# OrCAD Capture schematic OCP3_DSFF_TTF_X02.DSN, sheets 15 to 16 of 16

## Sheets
15 PAGE16 - 3V3 REGULATOR: size Custom
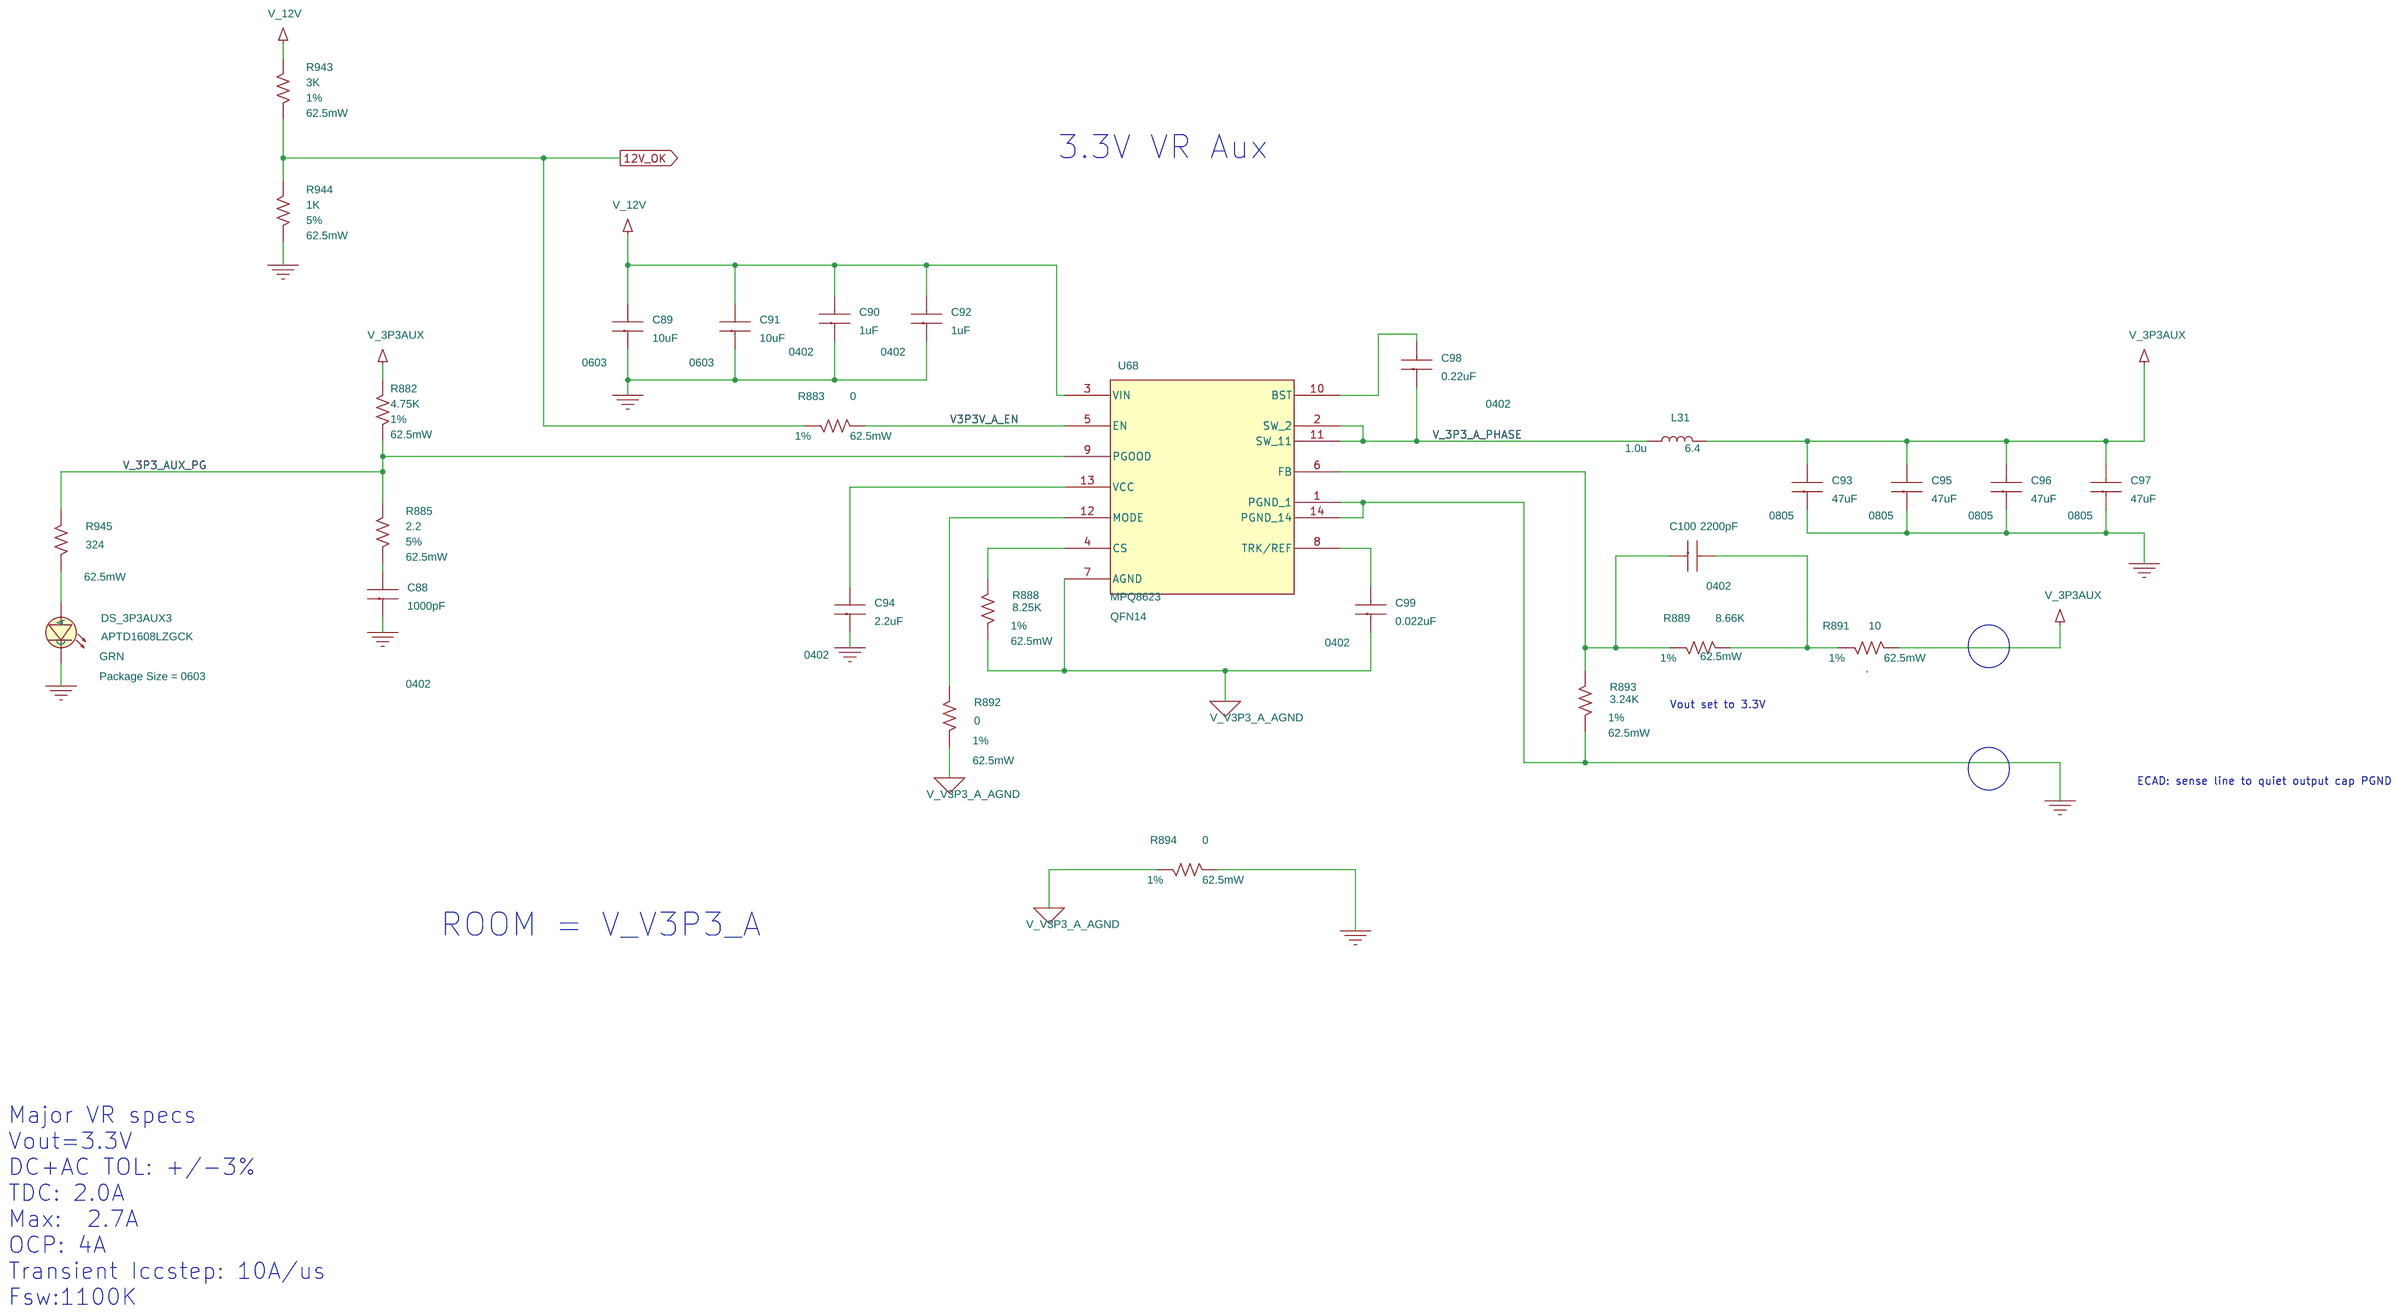
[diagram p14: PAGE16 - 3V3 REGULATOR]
16 PAGE09 - Secondary M-XIO/PICPWR: size Custom
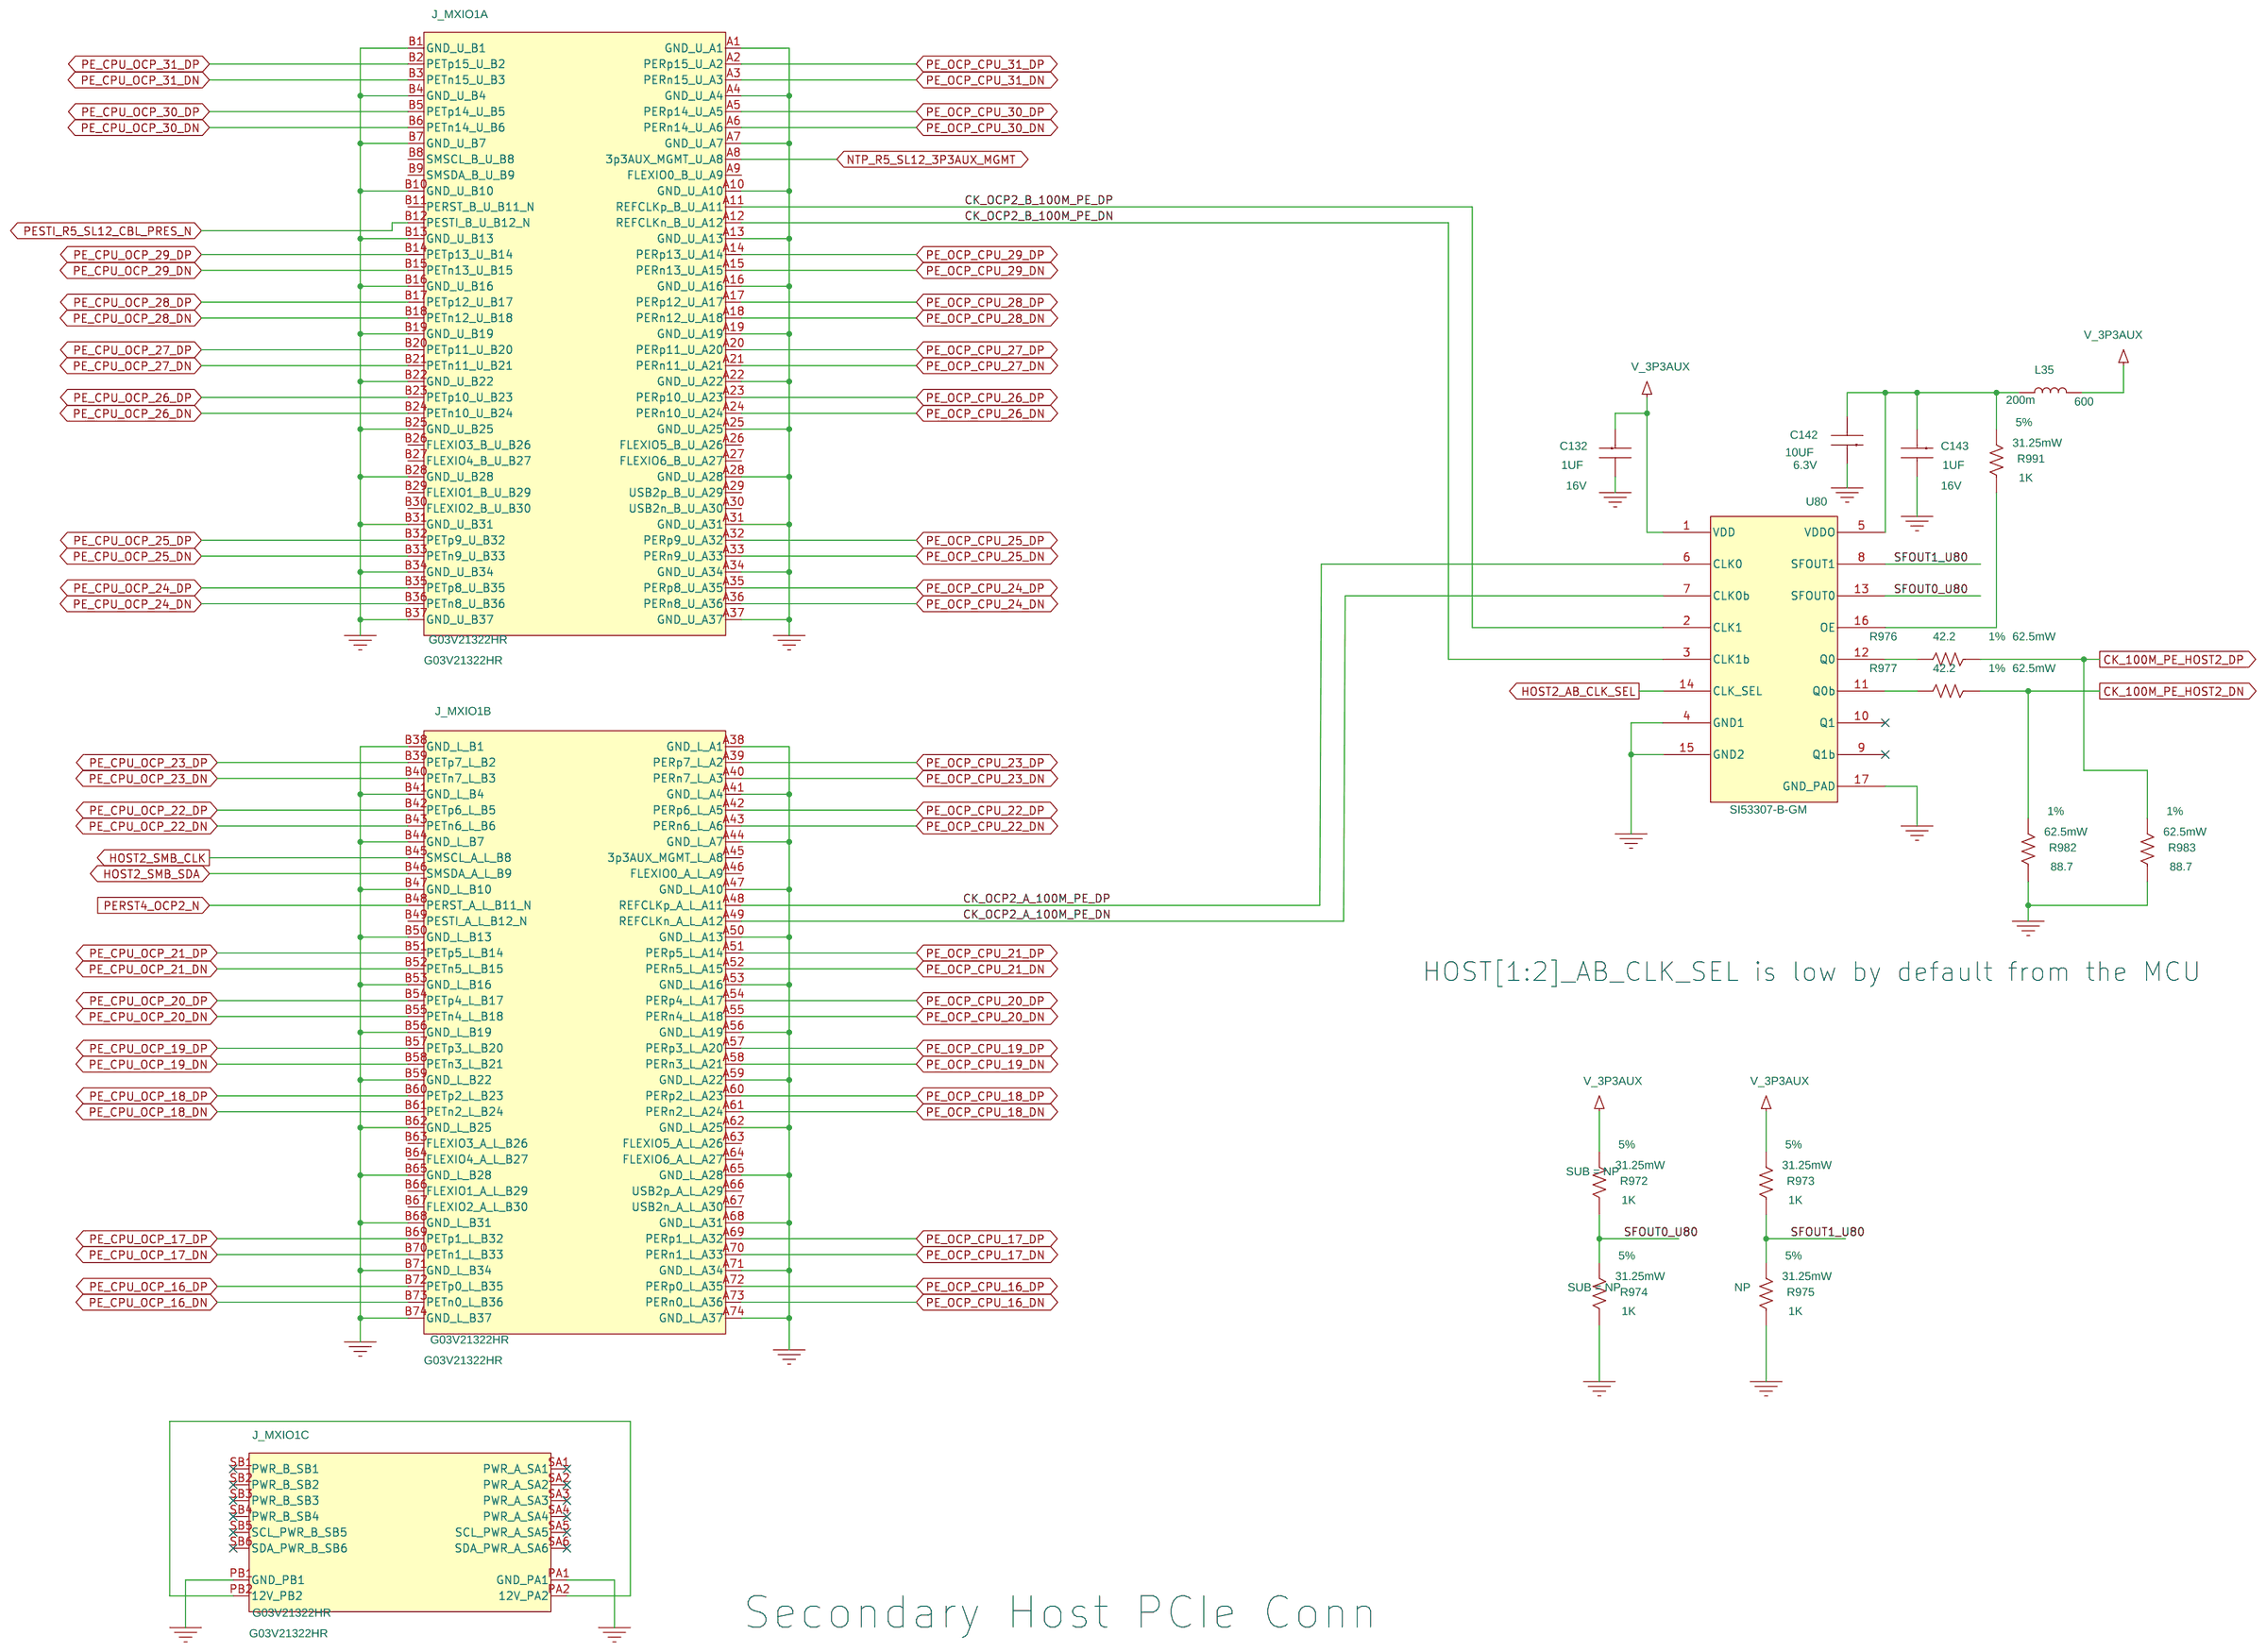
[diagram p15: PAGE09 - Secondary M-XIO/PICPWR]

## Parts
sheet PAGE09 - Secondary M-XIO/PICPWR
C132  1UF  [C0603]
C142  10UF  [C0603]
C143  1UF  [C0603]
J_MXIO1  G03V21322HR  [AMPHENOL_G03V21322HR]  (sections A,B,C)
L35  600  [FR0603]
R972  1K  [R0402]
R973  1K  [R0402]
R974  1K  [R0402]
R975  1K  [R0402]
R976  42.2  [R0402]
R977  42.2  [R0402]
R982  88.7  [R0402]
R983  88.7  [R0402]
R991  1K  [R0402]
U80  SI53307-B-GM  [QFN50P300X300X90-17]
sheet PAGE16 - 3V3 REGULATOR
C88  1000pF  [C0402_H22]
C89  10uF  [C0603]
C90  1uF  [C0402_H32]
C91  10uF  [C0603]
C92  1uF  [C0402_H32]
C93  47uF  [C0805]
C94  2.2uF  [C0402_H32]
C95  47uF  [C0805]
C96  47uF  [C0805]
C97  47uF  [C0805]
C98  0.22uF  [C0402_H22]
C99  0.022uF  [C0402_h22]
C100  2200pF  [C0402_H22]
DS_3P3AUX3  APTD1608LZGCK  [LEDC1608X95N]
L31  1.0u  [INDM_SPM5030_13G]
R882  4.75K  [R0402]
R883  0  [R0402]
R885  2.2  [R0402]
R888  8.25K  [R0402]
R889  8.66K  [R0402]
R891  10  [R0402]
R892  0  [R0402]
R893  3.24K  [R0402]
R894  0  [R0402]
R943  3K  [R0402]
R944  1K  [R0402]
R945  324  [R0402]
U68  mpq8623  [QFN50P200X300X100_14N]

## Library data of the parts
C132 C143 = cap: CAP,1UF,10%,16V,X7R,0603; DEVICE: 090729120352; Part Number: RY497; TOLERANCE: 10%; VOLTAGE: 16V
C142 = cap: CAP,10UF,20%,6.3V,X5R,0603; DEVICE: 090729120437; Part Number: YT654; ROOM: CKBUF; TOLERANCE: 20%; VOLTAGE: 6.3V
J_MXIO1 = G03V21322HR: CON,PCIE,160S+4P,F,V,G,SM,MCIO; Manufacturer: AMPHENOL; Package Height: 9.65 MM; Part Number: YHYWJ
L35 = g_ind: FE,BEAD,200MA,0603,600OHM@100M; DEVICE: 090729180941; Part Number: JW704; Rated Current: 200m
R972 R974 R975 = res: RES,1K,1/32W,5%,THKFLM,0402; DEVICE: 091106110100; Part Number: 92260; Rated Power: 31.25mW; SUB: NP; TOLERANCE: 5%
R973 R991 = res: RES,1K,1/32W,5%,THKFLM,0402; DEVICE: 091106110100; Part Number: 92260; Rated Power: 31.25mW; TOLERANCE: 5%
R976 R977 = res: RES,42.2,1/16W,1%,THKFLM,0402; DEVICE: 090729121124; Manufacturer: CYNTEC; Manufacturer PN: PFR05S42R2F; Package Height: 0.5334 MM; Part Number: G861N; ROOM: CKBUF; Rated Power: 62.5mW; TOLERANCE: 1%
R982 R983 = res: RES,88.7,1/16W,1%,THKFLM,0402; DEVICE: 091106110100; Manufacturer: SEI ELECTRONICS INC; Manufacturer PN: RMCF 1/16S 88.7 1%; Package Height: 0.5334 MM; Part Number: 98FVG; Rated Power: 62.5mW; TOLERANCE: 1%
U80 = SI53307-B-GM: IC,SI53307-B,QFN16,2OUT,CLKBUF; Manufacturer: SILICON LABORATORIES; Package Height: 0.9 MM; Part Number: GYG4F
C88 = cap: CAP,1000PF,10%,16V,X7R,0402; ALT_SYMBOLS: (SMX0402B); Dielectric Type: X7R; Manufacturer: KEMET ELECTRONICS; Manufacturer PN: C0402C102K4RAC; PACK_TYPE: 0402; Package Height: 0.5588 MM; Part Number: P8142; REQIDNO: 2996; Tolerance: 10%; Voltage: 16V
C89 C91 = cap: CAP,10UF,20%,16V,X6S,0603; Dielectric Type: X6S; Manufacturer: KYOCERA CORPORATION; Manufacturer PN: CM105X6S106M16AT; PACK_TYPE: 0603; Package Height: 0.9144 MM; Part Number: 3MRV8; REQIDNO: Q08TGJ044; Tolerance: 20%; Voltage: 16V
C90 C92 = cap: CAP,1UF,10%,16V,X6S,0402; ALT_SYMBOLS: (SMX0402B); Dielectric Type: X6S; Manufacturer: MURATA ERIE; Manufacturer PN: GRM155C81C105KE11; PACK_TYPE: 0402; Package Height: 0.8 MM; Part Number: R6D0N; REQIDNO: 2PHQRH9BD; Tolerance: 10%; Voltage: 16V
C93 C95-C97 = cap: CAP,47UF,20%,4V,X5R,0805; Dielectric Type: X5R; Manufacturer: KEMET ELECTRONICS; Manufacturer PN: C0805C476M7PACTU; PACK_TYPE: 0805; Package Height: 1.524 MM; Part Number: YTR1G; REQIDNO: LDSUXCPG8; Tolerance: 20%; Voltage: 4V
C94 = cap: CAP,2.2UF,10%,10V,X6S,0402; ALT_SYMBOLS: (SMX0402B); Dielectric Type: X6S; Manufacturer: MURATA ERIE; Manufacturer PN: GRM155C81A225KE44D; PACK_TYPE: 0402; Package Height: 0.8 MM; Part Number: F5NPN; REQIDNO: 57537LBE1; Tolerance: 10%; Voltage: 10V
C98 = cap: CAP,0.22UF,10%,16V,X7R,0402; Dielectric Type: X7R; Manufacturer: MURATA ERIE; Manufacturer PN: GRM155R71C224KA12D; PACK_TYPE: 0402; Package Height: 0.5588 MM; Part Number: VDX96; REQIDNO: 3608; Tolerance: 10%; Voltage: 16V
C99 = cap: CAP,0.022UF,10%,16V,X7R,0402; ALT_SYMBOLS: (SMX0402B); Dielectric Type: X7R; Manufacturer: MURATA ERIE; Manufacturer PN: GRM155R71C223KA01; PACK_TYPE: 0402; Package Height: 22 MIL; Part Number: C9767; REQIDNO: 1260; Tolerance: 10%; Voltage: 16V
C100 = cap: CAP,2200PF,10%,50V,X7R,0402; Dielectric Type: X7R; Manufacturer: KEMET ELECTRONICS; Manufacturer PN: C0402C222K5RAC; PACK_TYPE: 0402; Package Height: 0.5588 MM; Part Number: W3308; REQIDNO: 3683; Tolerance: 10%; Voltage: 50V
DS_3P3AUX3 = g_led_a1_c2: LED,0603,CLR,GRN,2.5V,2MA,SMD; CLASS: DISCRETE; DPN: P0HK6; LED Color: GRN; Lead Free: Yes; Lifecycle Phase: X Revision; Manufacturer: KINGBRIGHT CORPORATION; Package Height: 0.95 MM; Package Size: 0603; Package Type: SMD; Part Number: P0HK6; Rev: X00-00; Voltage: 2.5V
L31 = g_ind: IND,1UH,6.4A,20%,5X5; ALT_SYMBOLS: (INDM_SPM5030); DEVICE: 091014084804; Part Number: WRP19; ROOM: V_V3P3V_A; Rated Current: 6.4; SUBSYS: VR_VSB11_1P175_SW
R882 = res: RES,4.75K,1/16W,1%,THKFLM,0402; DEVICE: 090729121325; Part Number: T3502; ROOM: V_V3P3V_A; Rated Power: 62.5mW; SUBSYS: VR_VSB11_1P175_SW; TOLERANCE: 1%
R883 R894 = res: RES,0,1/16W,1%,THKFLM,0402; CLASS: DISCRETE; DEVICE: 090729120606; DPN: 9K341; Lead Free: Yes; Lifecycle Phase: A Revision; Manufacturer: SEI ELECTRONICS INC; Manufacturer PN: RMCF 1/16S 0 1%; Material: Thick Film; Package Height: 16 MIL; Package Size: 0402; Package Type: SMD; Part Number: 9K341; ROOM: V_V3P3V_A; Rated Power: 62.5mW; Rev: A00-00; SUBSYS: VR_VSB11_1P175_SW; TOLERANCE: 1%
R885 = res: RES,2.2,1/16W,5%,THKFLM,0402; DEVICE: 090729120551; Part Number: 6R626; ROOM: V_V3P3V_A; Rated Power: 62.5mW; TOLERANCE: 5%
R888 = res: RES,8.25K,1/16W,1%,THKFLM,0402; DEVICE: 090729121355; Part Number: U3669; ROOM: V_V3P3V_A; Rated Power: 62.5mW; SUBSYS: VR_VSB11_1P175_SW; TOLERANCE: 1%
R889 = res: RES,8.66K,1/16W,1%,THKFLM,0402; CLASS: DISCRETE; DEVICE: 090729120904; DPN: G9354; Lead Free: Yes; Lifecycle Phase: A Revision; Manufacturer: KOA; Manufacturer PN: RK73H1ET-8661F; Material: Thick Film; Package Height: 16 MIL; Package Size: 0402; Package Type: SMD; Part Number: G9354; ROOM: V_V3P3V_A; Rated Power: 62.5mW; Rev: A00-00; SUBSYS: VR_VSB11_1P175_SW; TOLERANCE: 1%
R891 = res: RES,10,1/16W,1%,THKFLM,0402; DEVICE: 090729120605; Part Number: 933NH; ROOM: V_V3P3V_A; Rated Power: 62.5mW; SUBSYS: VR_VSB11_1P175_SW; TOLERANCE: 1%
R892 = res: RES,0,1/16W,1%,THKFLM,0402; ALT_SYMBOLS: (SMX0402B); DEVICE: 090729120807; Manufacturer: SEI ELECTRONICS INC; Manufacturer PN: RMCF 1/16S 0 1%; Package Height: 0.5334 MM; Part Number: 9K341; ROOM: V_V3P3V_A; Rated Power: 62.5mW; SUB: NP; SUBSYS: VR_VSB11_1P175_SW; TOLERANCE: 1%
R893 = res: RES,3.24K,1/16W,1%,THKFLM,0402; CLASS: DISCRETE; DEVICE: 090729120802; DPN: J8825; Lead Free: Yes; Lifecycle Phase: A Revision; Manufacturer: KOA; Manufacturer PN: RK73H1ETTP3241F; Material: Thick Film; Package Height: 16 MIL; Package Size: 0402; Package Type: SMD; Part Number: J8825; ROOM: V_V3P3V_A; Rated Power: 62.5mW; Rev: A00-00; SUBSYS: VR_VSB11_1P175_SW; TOLERANCE: 1%
R943 = res: RES,3K,1/16W,1%,THKFLM,0402; DEVICE: 090729121325; Package Height: 0.5334 MM; Part Number: F981G; ROOM: V_V3P3V_A; Rated Power: 62.5mW; SUBSYS: VR_VSB11_1P175_SW; TOLERANCE: 1%
R944 = res: RES,1K,1/16W,5%,THKFLM,0402; DEVICE: 090729120551; Manufacturer: KOA; Manufacturer PN: RK73B1ETTP102J; Package Height: 0.5334 MM; Part Number: J5741; ROOM: V_V3P3V_A; Rated Power: 62.5mW; TOLERANCE: 5%
R945 = res: RES,324,1/16W,1%,THKFLM,0402; CLASS: DISCRETE; DPN: D9921; Lead Free: Yes; Lifecycle Phase: A Revision; Manufacturer: KOA; Manufacturer PN: RK73H1ETTP3240F; Package Height: 16 MIL; Package Size: 0402; Package Type: SMD; Part Number: D9921; Rated Power: 62.5mW; Rev: A00-00; Tolerance: 1%
U68 = mpq8623: IC,MPQ8623,QFN14,CONVERTER; DEVICE: 150306131512; Part Number: 3J7PR; ROOM: V_V3P3V_A; SUBSYS: VR_VSB11_1P175_SW; TAG1: MPQ8623; TAG2: QFN14

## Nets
12V_OK: R883.1 R943.1 R944.2 ; also on sheet 13
GND: C88.1 C89.1 C90.1 C91.1 C92.1 C93.1 C94.1 C95.1 C96.1 C97.1 C132.2 C142.1 C143.2 DS_3P3AUX3.2(C) J_MXIO1.A1(GND_U) J_MXIO1.A4(GND_U) J_MXIO1.A7(GND_U) J_MXIO1.A10(GND_U) J_MXIO1.A13(GND_U) J_MXIO1.A16(GND_U) J_MXIO1.A19(GND_U) J_MXIO1.A22(GND_U) J_MXIO1.A25(GND_U) J_MXIO1.A28(GND_U) J_MXIO1.A31(GND_U) J_MXIO1.A34(GND_U) J_MXIO1.A37(GND_U) J_MXIO1.A38(GND_L_A1) J_MXIO1.A41(GND_L_A4) J_MXIO1.A44(GND_L_A7) J_MXIO1.A47(GND_L_A10) J_MXIO1.A50(GND_L_A13) J_MXIO1.A53(GND_L_A16) J_MXIO1.A56(GND_L_A19) J_MXIO1.A59(GND_L_A22) J_MXIO1.A62(GND_L_A25) J_MXIO1.A65(GND_L_A28) J_MXIO1.A68(GND_L_A31) J_MXIO1.A71(GND_L_A34) J_MXIO1.A74(GND_L_A37) J_MXIO1.B1(GND_U) J_MXIO1.B4(GND_U) J_MXIO1.B7(GND_U) J_MXIO1.B10(GND_U) J_MXIO1.B13(GND_U) J_MXIO1.B16(GND_U) J_MXIO1.B19(GND_U) J_MXIO1.B22(GND_U) J_MXIO1.B25(GND_U) J_MXIO1.B28(GND_U) J_MXIO1.B31(GND_U) J_MXIO1.B34(GND_U) J_MXIO1.B37(GND_U) J_MXIO1.B38(GND_L_B1) J_MXIO1.B41(GND_L_B4) J_MXIO1.B44(GND_L_B7) J_MXIO1.B47(GND_L_B10) J_MXIO1.B50(GND_L_B13) J_MXIO1.B53(GND_L_B16) J_MXIO1.B56(GND_L_B19) J_MXIO1.B59(GND_L_B22) J_MXIO1.B62(GND_L_B25) J_MXIO1.B65(GND_L_B28) J_MXIO1.B68(GND_L_B31) J_MXIO1.B71(GND_L_B34) J_MXIO1.B74(GND_L_B37) J_MXIO1.PA1(GND) J_MXIO1.PB1(GND) R893.1 R894.2 R944.1 R974.1 R975.1 R982.1 R983.1 U68.1(PGND) U68.14(PGND) U80.4(GND1) U80.15(GND2) U80.17(GND_PAD) ; also on sheet 4 5 6 7 8 10 11 12 13 14
V3P3V_A_EN: R883.2 U68.5(EN)
CK_100M_PE_HOST2_DN: R977.1 R982.2 ; also on sheet 14
CK_100M_PE_HOST2_DP: R976.1 R983.2 ; also on sheet 14
CK_OCP2_A_100M_PE_DN: J_MXIO1.A49(REFCLKn_A_L_A12) U80.7(CLK0b)
CK_OCP2_A_100M_PE_DP: J_MXIO1.A48(REFCLKp_A_L_A11) U80.6(CLK0)
CK_OCP2_B_100M_PE_DN: J_MXIO1.A12(REFCLKn_B_U) U80.3(CLK1b)
CK_OCP2_B_100M_PE_DP: J_MXIO1.A11(REFCLKp_B_U) U80.2(CLK1)
HOST2_AB_CLK_SEL: U80.14(CLK_SEL) ; also on sheet 5
HOST2_SMB_CLK: J_MXIO1.B45(SMSCL_A_L_B8) ; also on sheet 5
HOST2_SMB_SDA: J_MXIO1.B46(SMSDA_A_L_B9) ; also on sheet 5
NTP_R5_SL12_3P3AUX_MGMT: J_MXIO1.A8(3p3AUX_MGMT_U)
PE_CPU_OCP_16_DN: J_MXIO1.B73(PETn0_L_B36) ; also on sheet 7
PE_CPU_OCP_16_DP: J_MXIO1.B72(PETp0_L_B35) ; also on sheet 7
PE_CPU_OCP_17_DN: J_MXIO1.B70(PETn1_L_B33) ; also on sheet 7
PE_CPU_OCP_17_DP: J_MXIO1.B69(PETp1_L_B32) ; also on sheet 7
PE_CPU_OCP_18_DN: J_MXIO1.B61(PETn2_L_B24) ; also on sheet 7
PE_CPU_OCP_18_DP: J_MXIO1.B60(PETp2_L_B23) ; also on sheet 7
PE_CPU_OCP_19_DN: J_MXIO1.B58(PETn3_L_B21) ; also on sheet 7
PE_CPU_OCP_19_DP: J_MXIO1.B57(PETp3_L_B20) ; also on sheet 7
PE_CPU_OCP_20_DN: J_MXIO1.B55(PETn4_L_B18) ; also on sheet 7
PE_CPU_OCP_20_DP: J_MXIO1.B54(PETp4_L_B17) ; also on sheet 7
PE_CPU_OCP_21_DN: J_MXIO1.B52(PETn5_L_B15) ; also on sheet 7
PE_CPU_OCP_21_DP: J_MXIO1.B51(PETp5_L_B14) ; also on sheet 7
PE_CPU_OCP_22_DN: J_MXIO1.B43(PETn6_L_B6) ; also on sheet 7
PE_CPU_OCP_22_DP: J_MXIO1.B42(PETp6_L_B5) ; also on sheet 7
PE_CPU_OCP_23_DN: J_MXIO1.B40(PETn7_L_B3) ; also on sheet 7
PE_CPU_OCP_23_DP: J_MXIO1.B39(PETp7_L_B2) ; also on sheet 7
PE_CPU_OCP_24_DN: J_MXIO1.B36(PETn8_U) ; also on sheet 7
PE_CPU_OCP_24_DP: J_MXIO1.B35(PETp8_U) ; also on sheet 7
PE_CPU_OCP_25_DN: J_MXIO1.B33(PETn9_U) ; also on sheet 7
PE_CPU_OCP_25_DP: J_MXIO1.B32(PETp9_U) ; also on sheet 7
PE_CPU_OCP_26_DN: J_MXIO1.B24(PETn10_U) ; also on sheet 7
PE_CPU_OCP_26_DP: J_MXIO1.B23(PETp10_U) ; also on sheet 7
PE_CPU_OCP_27_DN: J_MXIO1.B21(PETn11_U) ; also on sheet 7
PE_CPU_OCP_27_DP: J_MXIO1.B20(PETp11_U) ; also on sheet 7
PE_CPU_OCP_28_DN: J_MXIO1.B18(PETn12_U) ; also on sheet 7
PE_CPU_OCP_28_DP: J_MXIO1.B17(PETp12_U) ; also on sheet 7
PE_CPU_OCP_29_DN: J_MXIO1.B15(PETn13_U) ; also on sheet 7
PE_CPU_OCP_29_DP: J_MXIO1.B14(PETp13_U) ; also on sheet 7
PE_CPU_OCP_30_DN: J_MXIO1.B6(PETn14_U) ; also on sheet 7
PE_CPU_OCP_30_DP: J_MXIO1.B5(PETp14_U) ; also on sheet 7
PE_CPU_OCP_31_DN: J_MXIO1.B3(PETn15_U) ; also on sheet 7
PE_CPU_OCP_31_DP: J_MXIO1.B2(PETp15_U) ; also on sheet 7
PE_OCP_CPU_16_DN: J_MXIO1.A73(PERn0_L_A36) ; also on sheet 7
PE_OCP_CPU_16_DP: J_MXIO1.A72(PERp0_L_A35) ; also on sheet 7
PE_OCP_CPU_17_DN: J_MXIO1.A70(PERn1_L_A33) ; also on sheet 7
PE_OCP_CPU_17_DP: J_MXIO1.A69(PERp1_L_A32) ; also on sheet 7
PE_OCP_CPU_18_DN: J_MXIO1.A61(PERn2_L_A24) ; also on sheet 7
PE_OCP_CPU_18_DP: J_MXIO1.A60(PERp2_L_A23) ; also on sheet 7
PE_OCP_CPU_19_DN: J_MXIO1.A58(PERn3_L_A21) ; also on sheet 7
PE_OCP_CPU_19_DP: J_MXIO1.A57(PERp3_L_A20) ; also on sheet 7
PE_OCP_CPU_20_DN: J_MXIO1.A55(PERn4_L_A18) ; also on sheet 7
PE_OCP_CPU_20_DP: J_MXIO1.A54(PERp4_L_A17) ; also on sheet 7
PE_OCP_CPU_21_DN: J_MXIO1.A52(PERn5_L_A15) ; also on sheet 7
PE_OCP_CPU_21_DP: J_MXIO1.A51(PERp5_L_A14) ; also on sheet 7
PE_OCP_CPU_22_DN: J_MXIO1.A43(PERn6_L_A6) ; also on sheet 7
PE_OCP_CPU_22_DP: J_MXIO1.A42(PERp6_L_A5) ; also on sheet 7
PE_OCP_CPU_23_DN: J_MXIO1.A40(PERn7_L_A3) ; also on sheet 7
PE_OCP_CPU_23_DP: J_MXIO1.A39(PERp7_L_A2) ; also on sheet 7
PE_OCP_CPU_24_DN: J_MXIO1.A36(PERn8_U) ; also on sheet 7
PE_OCP_CPU_24_DP: J_MXIO1.A35(PERp8_U) ; also on sheet 7
PE_OCP_CPU_25_DN: J_MXIO1.A33(PERn9_U) ; also on sheet 7
PE_OCP_CPU_25_DP: J_MXIO1.A32(PERp9_U) ; also on sheet 7
PE_OCP_CPU_26_DN: J_MXIO1.A24(PERn10_U) ; also on sheet 7
PE_OCP_CPU_26_DP: J_MXIO1.A23(PERp10_U) ; also on sheet 7
PE_OCP_CPU_27_DN: J_MXIO1.A21(PERn11_U) ; also on sheet 7
PE_OCP_CPU_27_DP: J_MXIO1.A20(PERp11_U) ; also on sheet 7
PE_OCP_CPU_28_DN: J_MXIO1.A18(PERn12_U) ; also on sheet 7
PE_OCP_CPU_28_DP: J_MXIO1.A17(PERp12_U) ; also on sheet 7
PE_OCP_CPU_29_DN: J_MXIO1.A15(PERn13_U) ; also on sheet 7
PE_OCP_CPU_29_DP: J_MXIO1.A14(PERp13_U) ; also on sheet 7
PE_OCP_CPU_30_DN: J_MXIO1.A6(PERn14_U) ; also on sheet 7
PE_OCP_CPU_30_DP: J_MXIO1.A5(PERp14_U) ; also on sheet 7
PE_OCP_CPU_31_DN: J_MXIO1.A3(PERn15_U) ; also on sheet 7
PE_OCP_CPU_31_DP: J_MXIO1.A2(PERp15_U) ; also on sheet 7
PERST4_OCP2_N: J_MXIO1.B48(PERST_A_L_B11_N) ; also on sheet 5 7
PESTI_R5_SL12_CBL_PRES_N: J_MXIO1.B12(PESTI_B_U_B12_N) ; also on sheet 8
SFOUT0_U80: R972.1 R974.2 U80.13(SFOUT0)
SFOUT1_U80: R973.1 R975.2 U80.8(SFOUT1)
V_3P3_A_PHASE: C98.1 L31.1 U68.2(SW) U68.11(SW)
V_3P3_AUX_PG: R882.1 R885.2 R945.2 U68.9(PGOOD)
V_3P3AUX: C93.2 C95.2 C96.2 C97.2 C132.1 L31.2 L35.1 R882.2 R891.2 R972.2 R973.2 U80.1(VDD) ; also on sheet 4 5 6 7 8 10 11 12 13 14
V_12V: C89.2 C90.2 C91.2 C92.2 R943.2 U68.3(VIN) ; also on sheet 4 6 7 13
V_V3P3_A_AGND: C99.1 R888.1 R892.1 R894.1 U68.7(AGND)
N17152561: J_MXIO1.PA2(12V) J_MXIO1.PB2(12V)
N17172428: C98.2 U68.10(BST)
N17172473: C100.1 R889.1 R893.2 U68.6(FB)
N17172505: C99.2 U68.8(TRK/REF)
N17172513: C100.2 R889.2 R891.1
N17172928: C94.2 U68.13(VCC)
N17172942: R892.2 U68.12(MODE)
N17172948: R888.2 U68.4(CS)
N17172952: C88.2 R885.1
N17255259: DS_3P3AUX3.1(A) R945.1
N17293632: R991.1 U80.16(OE)
N17322639: R976.2 U80.12(Q0)
N17322671: R977.2 U80.11(Q0b)
N17394212: C142.2 C143.1 L35.2 R991.2 U80.5(VDDO)

Not connected (* = marked no-connect by the designer): J_MXIO1 A9(FLEXIO0_B_U) A26(FLEXIO5_B_U) A27(FLEXIO6_B_U) A29(USB2p_B_U) A30(USB2n_B_U) A45(3p3AUX_MGMT_L_A8) A46(FLEXIO0_A_L_A9) A63(FLEXIO5_A_L_A26) A64(FLEXIO6_A_L_A27) A66(USB2p_A_L_A29) A67(USB2n_A_L_A30) B8(SMSCL_B_U) B9(SMSDA_B_U) B11(PERST_B_U_B11_N) B26(FLEXIO3_B_U) B27(FLEXIO4_B_U) B29(FLEXIO1_B_U) B30(FLEXIO2_B_U) B49(PESTI_A_L_B12_N) B63(FLEXIO3_A_L_B26) B64(FLEXIO4_A_L_B27) B66(FLEXIO1_A_L_B29) B67(FLEXIO2_A_L_B30) SA1(PWR_A)* SA2(PWR_A)* SA3(PWR_A)* SA4(PWR_A)* SA5(SCL_PWR_A)* SA6(SDA_PWR_A)* SB1(PWR_B)* SB2(PWR_B)* SB3(PWR_B)* SB4(PWR_B)* SB5(SCL_PWR_B)* SB6(SDA_PWR_B)*; U80 9(Q1b)* 10(Q1)*

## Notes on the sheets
sheet 15
- 3.3V VR Aux
- Vout set to 3.3V
- ECAD: sense line to quiet output cap PGND
- ROOM = V_V3P3_A
- Major VR specs
  Vout=3.3V
  DC+AC TOL: +/-3%
  TDC: 2.0A
  Max:  2.7A
  OCP: 4A
  Transient Iccstep: 10A/us
  Fsw:1100K
sheet 16
- HOST[1:2]_AB_CLK_SEL is low by default from the MCU
- Secondary Host PCIe Conn
